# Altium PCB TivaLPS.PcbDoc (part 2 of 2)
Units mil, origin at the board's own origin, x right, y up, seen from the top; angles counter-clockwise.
Board outline 2370 x 2970 mil, 2 copper layers (TopLayer, BottomLayer), stack 30.45 mil thick; 141 components, 125 nets, 734 pads, 136 vias.
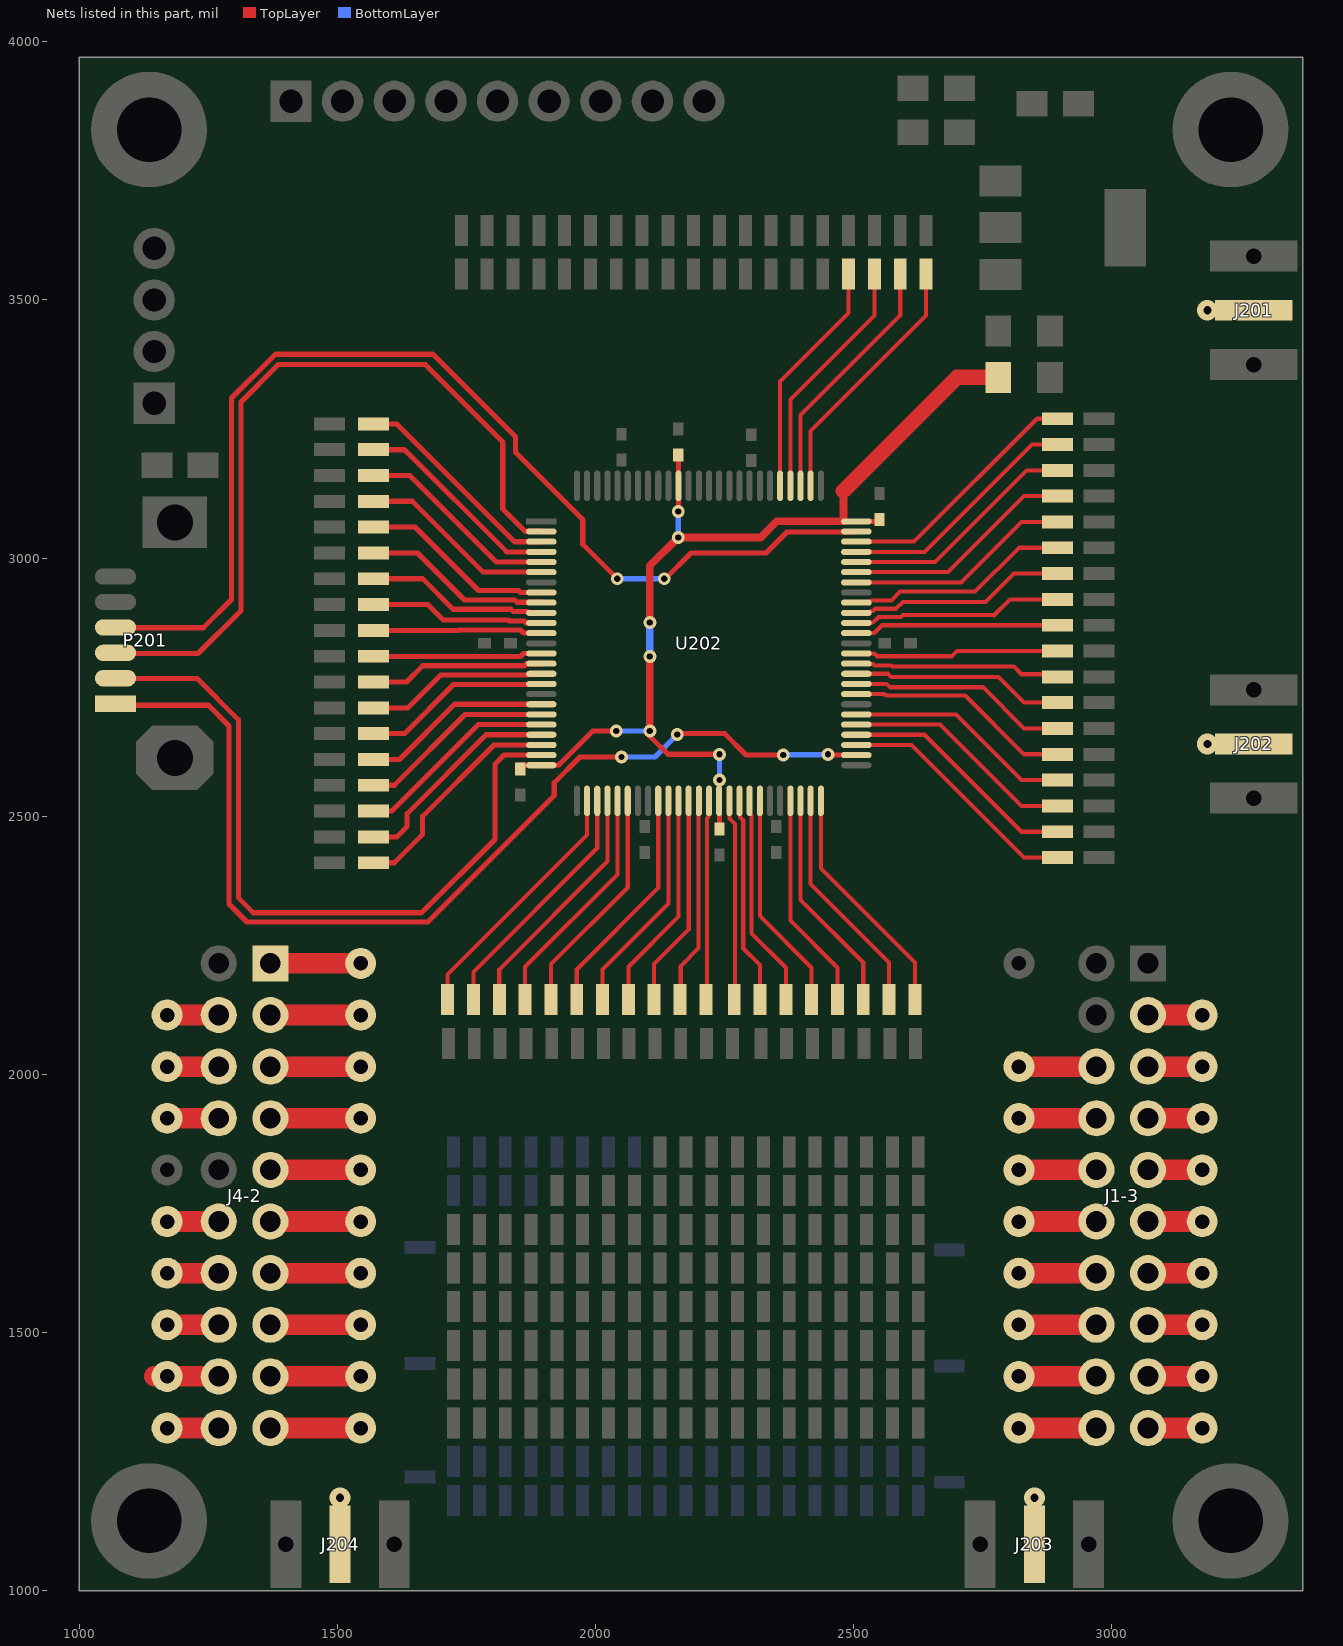
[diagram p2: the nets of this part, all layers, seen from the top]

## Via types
v1: diameter 25, hole 12, TopLayer to BottomLayer, 115 vias
v2: diameter 40, hole 16, TopLayer to BottomLayer, 19 vias
v3: diameter 40, hole 16, TopLayer to BottomLayer, tented top, 2 vias

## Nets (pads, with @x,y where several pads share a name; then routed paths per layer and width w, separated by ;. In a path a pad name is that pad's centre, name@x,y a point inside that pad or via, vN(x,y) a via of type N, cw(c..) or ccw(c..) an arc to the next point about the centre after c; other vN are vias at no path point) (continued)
NetTP216_1: TP216.1 U202.80 | length 464.8
  TopLayer w8: U202.80@2357.48,3140.12 2357.48,3342.48 2490,3475 TP216.1@2490,3550
NetTP217_1: TP217.1 U202.79 | length 477.3
  TopLayer w8: U202.79@2377.17,3140.12 2377.17,3307.17 2540,3470 TP217.1@2540,3550
NetTP218_1: TP218.1 U202.78 | length 489.9
  TopLayer w8: U202.78@2396.85,3140.12 2396.85,3276.85 2590,3470 TP218.1@2590,3550
NetTP219_1: TP219.1 U202.77 | length 502.4
  TopLayer w8: U202.77@2416.54,3140.12 2416.54,3246.54 2640,3470 TP219.1@2640,3550
NetTP233_1: TP233.1 U202.3 | length 419.4
  TopLayer w10: TP233.1@1570,3260 1615,3260 1843.15,3031.85 U202.3@1894.88,3031.85
NetTP234_1: TP234.1 U202.73 | length 488.5
  TopLayer w8: U202.73@2505.12,3031.85 2616.85,3031.85 2855,3270 TP234.1@2895,3270
NetTP237_1: TP237.1 U202.4 | length 406.8
  TopLayer w10: TP237.1@1570,3210 1630.04,3210 1827.88,3012.17 U202.4@1894.88,3012.17
NetTP238_1: TP238.1 U202.72 | length 476
  TopLayer w8: U202.72@2505.12,3012.17 2637.17,3012.17 2845,3220 TP238.1@2895,3220
NetTP241_1: TP241.1 U202.5 | length 394.3
  TopLayer w10: TP241.1@1570,3160 1640,3160 1807.52,2992.48 U202.5@1894.88,2992.48
NetTP242_1: TP242.1 U202.71 | length 463.4
  TopLayer w8: U202.71@2505.12,2992.48 2657.48,2992.48 2835,3170 TP242.1@2895,3170
NetTP243_1: TP243.1 U202.6 | length 381.7
  TopLayer w10: TP243.1@1570,3110 1645,3110 1782.2,2972.8 U202.6@1894.88,2972.8
NetTP244_1: TP244.1 U202.70 | length 450.9
  TopLayer w8: U202.70@2505.12,2972.8 2682.8,2972.8 2830,3120 TP244.1@2895,3120
NetTP245_1: TP245.1 U202.69 | length 438.3
  TopLayer w8: U202.69@2505.12,2953.11 2708.11,2953.11 2825,3070 TP245.1@2895,3070
NetTP246_1: TP246.1 U202.8 | length 377.3
  TopLayer w10: TP246.1@1570,3060 1650,3060 1773,2937 1850.71,2937 1854.28,2933.43 U202.8@1894.88,2933.43
NetTP247_1: TP247.1 U202.9 | length 364.8
  TopLayer w10: TP247.1@1570,3010 1655,3010 1746,2919 1843.25,2919 1847.75,2914.5 1894.12,2914.5 U202.9@1894.88,2913.74
NetTP248_1: TP248.1 U202.67 | length 433.9
  TopLayer w8: U202.67@2505.12,2913.74 2529.77,2913.74 2534.03,2918 2573,2918 2590,2935 2735,2935 2820,3020 TP248.1@2895,3020
NetTP249_1: TP249.1 U202.10 | length 352.2
  TopLayer w10: TP249.1@1570,2960 1665,2960 1724,2901 1835.8,2901 1840.3,2896.5 1868.32,2896.5 1870.42,2894.4 1894.54,2894.4 U202.10@1894.88,2894.06
NetTP250_1: TP250.1 U202.66 | length 421.3
  TopLayer w8: U202.66@2505.12,2894.06 2529.77,2894.06 2533.46,2897.74 2537.49,2897.74 2541.75,2902 2582,2902 2595,2915 2755,2915 2810,2970 TP250.1@2895,2970
NetTP251_1: TP251.1 U202.11 | length 339.6
  TopLayer w10: TP251.1@1570,2910 1675,2910 1705,2880 1831.34,2880 1832.84,2878.5 1861.96,2878.5 1865.74,2874.72 1894.54,2874.72 U202.11@1894.88,2874.37
NetTP252_1: TP252.1 U202.65 | length 409.4
  TopLayer w8: U202.65@2505.12,2874.37 2505.85,2875.1 2537.47,2875.1 2548.37,2886 2591,2886 2595,2890 2771,2890 2771.69,2889.31 2802.37,2920 TP252.1@2895,2920
NetTP253_1: TP253.1 U202.12 | length 327.5
  TopLayer w10: TP253.1@1570,2860 1733.94,2860 1734.44,2860.5 1854.5,2860.5 1860.32,2854.69 U202.12@1894.88,2854.69
NetTP254_1: TP254.1 U202.64 | length 396.2
  TopLayer w8: U202.64@2505.12,2854.69 2539.68,2854.69 2555,2870 TP254.1@2895,2870
NetTP255_1: TP255.1 U202.14 | length 327.5
  TopLayer w10: TP255.1@1570,2810 1570.5,2809.5 1854.5,2809.5 1860.32,2815.32 U202.14@1894.88,2815.32
NetTP256_1: TP256.1 U202.62 | length 396.2
  TopLayer w8: U202.62@2505.12,2815.32 2539.68,2815.32 2545,2810 2690,2810 2700,2820 TP256.1@2895,2820
NetTP258_1: TP258.1 U202.15 | length 339.6
  TopLayer w10: TP258.1@1570,2760 1633.5,2760 1665,2791.5 1861.96,2791.5 1865.74,2795.28 1894.54,2795.28 U202.15@1894.88,2795.63
NetTP259_1: TP259.1 U202.61 | length 400.5
  TopLayer w8: U202.61@2505.12,2795.63 2505.85,2794.9 2537.47,2794.9 2540.43,2791.95 2573.06,2791.95 2575,2790 2810,2790 2825,2775 2890,2775 TP259.1@2895,2770
NetTP262_1: TP262.1 U202.16 | length 352.2
  TopLayer w10: TP262.1@1570,2710 1636.5,2710 1700,2773.5 1868.32,2773.5 1870.42,2775.6 1894.54,2775.6 U202.16@1894.88,2775.95
NetTP263_1: TP263.1 U202.60 | length 413.1
  TopLayer w8: U202.60@2505.12,2775.95 2566.68,2775.95 2572.63,2770 2780,2770 2830,2720 TP263.1@2895,2720
NetTP266_1: TP266.1 U202.17 | length 364.8
  TopLayer w10: TP266.1@1570,2660 1630,2660 1725,2755 1847.25,2755 1847.75,2755.5 1894.12,2755.5 U202.17@1894.88,2756.26
NetTP267_1: TP267.1 U202.59 | length 425.6
  TopLayer w8: U202.59@2505.12,2756.26 2563.74,2756.26 2570,2750 2750,2750 2830,2670 TP267.1@2895,2670
NetTP270_1: TP270.1 U202.58 | length 438.2
  TopLayer w8: U202.58@2505.12,2736.57 2558.43,2736.57 2560,2735 2562.37,2735 2563.37,2734 2716,2734 2830,2620 TP270.1@2895,2620
NetTP273_1: TP273.1 U202.19 | length 369.2
  TopLayer w10: TP273.1@1570,2610 1620,2610 1726.89,2716.89 U202.19@1894.88,2716.89
NetTP276_1: TP276.1 U202.20 | length 381.7
  TopLayer w10: TP276.1@1570,2560 1610,2560 1747.2,2697.2 U202.20@1894.88,2697.2
NetTP277_1: TP277.1 U202.56 | length 442.6
  TopLayer w8: U202.56@2505.12,2697.2 2697.8,2697.2 2825,2570 TP277.1@2895,2570
NetTP280_1: TP280.1 U202.21 | length 394.3
  TopLayer w10: TP280.1@1570,2510 1605,2510 1772.52,2677.52 U202.21@1894.88,2677.52
NetTP281_1: TP281.1 U202.55 | length 455.1
  TopLayer w8: U202.55@2505.12,2677.52 2667.48,2677.52 2825,2520 TP281.1@2895,2520
NetTP284_1: TP284.1 U202.22 | length 421.5
  TopLayer w10: TP284.1@1570,2460 1615,2460 1635,2480 1635,2505 1787.83,2657.83 U202.22@1894.88,2657.83
NetTP285_1: TP285.1 U202.54 | length 467.7
  TopLayer w8: U202.54@2505.12,2657.83 2637.17,2657.83 2825,2470 TP285.1@2895,2470
NetTP288_1: TP288.1 U202.23 | length 439.9
  TopLayer w10: TP288.1@1570,2410 1610,2410 1665,2465 1665,2500 1803.15,2638.15 U202.23@1894.88,2638.15
NetTP289_1: TP289.1 U202.53 | length 480.2
  TopLayer w8: U202.53@2505.12,2638.15 2611.85,2638.15 2830,2420 TP289.1@2895,2420
NetTP292_1: TP292.1 U202.27 | length 496.7
  TopLayer w8: TP292.1@1713.46,2145.06 1713.46,2193.46 1983.46,2463.46 U202.27@1983.46,2529.88
NetTP293_1: TP293.1 U202.28 | length 484.1
  TopLayer w8: TP293.1@1763.46,2145.06 1763.46,2198.46 2003.15,2438.15 U202.28@2003.15,2529.88
NetTP294_1: TP294.1 U202.29 | length 471.5
  TopLayer w8: TP294.1@1813.46,2145.06 1813.46,2203.46 2022.83,2412.83 U202.29@2022.83,2529.88
NetTP295_1: TP295.1 U202.30 | length 459
  TopLayer w8: TP295.1@1863.46,2145.06 1863.46,2208.46 2042.52,2387.52 U202.30@2042.52,2529.88
NetTP296_1: TP296.1 U202.31 | length 446.4
  TopLayer w8: TP296.1@1913.46,2145.06 1913.46,2213.46 2062.2,2362.2 U202.31@2062.2,2529.88
NetTP297_1: TP297.1 U202.34 | length 450.2
  TopLayer w8: TP297.1@1963.46,2145.06 1963.46,2203.46 2121.26,2361.26 U202.34@2121.26,2529.88
NetTP298_1: TP298.1 U202.35 | length 437.6
  TopLayer w8: TP298.1@2013.46,2145.06 2013.46,2203.46 2140.94,2330.95 U202.35@2140.94,2529.88
NetTP299_1: TP299.1 U202.36 | length 425.1
  TopLayer w8: TP299.1@2063.46,2145.06 2063.46,2208.46 2160.63,2305.63 U202.36@2160.63,2529.88
NetTP300_1: TP300.1 U202.37 | length 412.5
  TopLayer w8: TP300.1@2113.46,2145.06 2113.46,2213.46 2180.32,2280.32 U202.37@2180.32,2529.88
NetTP301_1: TP301.1 U202.38 | length 400
  TopLayer w8: TP301.1@2163.46,2145.06 2165,2146.61 2165,2210 2199.5,2244.5 2199.5,2529.38 U202.38@2200,2529.88
NetTP302_1: TP302.1 U202.39 | length 387.4
  TopLayer w8: TP302.1@2213.46,2145.06 2215.5,2147.11 2215.5,2495.5 2218.96,2498.96 2218.96,2529.15 U202.39@2219.68,2529.88
NetTP303_1: TP303.1 U202.41 | length 390
  TopLayer w8: U202.41@2259.06,2529.88 2259.06,2495.95 2270,2485 2270,2146.61 TP303.1@2268.46,2145.06
NetTP304_1: TP304.1 U202.42 | length 401.3
  TopLayer w8: U202.42@2278.74,2529.88 2279.47,2529.15 2279.47,2498.16 2286,2491.63 2286,2244 2318.46,2211.54 TP304.1@2318.46,2145.06
NetTP305_1: TP305.1 U202.43 | length 413.8
  TopLayer w8: U202.43@2298.43,2529.88 2298.43,2505.23 2302,2501.65 2302,2273 2368.46,2206.54 TP305.1@2368.46,2145.06
NetTP306_1: TP306.1 U202.44 | length 426.4
  TopLayer w8: U202.44@2318.11,2529.88 2318.11,2306.89 2418.46,2206.54 TP306.1@2418.46,2145.06
NetTP307_1: TP307.1 U202.47 | length 422.6
  TopLayer w8: U202.47@2377.17,2529.88 2377.17,2297.83 2468.46,2206.54 TP307.1@2468.46,2145.06
NetTP308_1: TP308.1 U202.48 | length 435.2
  TopLayer w8: U202.48@2396.85,2529.88 2396.85,2338.15 2518.46,2216.54 TP308.1@2518.46,2145.06
NetTP309_1: TP309.1 U202.49 | length 447.7
  TopLayer w8: U202.49@2416.54,2529.88 2416.54,2368.46 2568.46,2216.54 TP309.1@2568.46,2145.06
NetTP310_1: TP310.1 U202.50 | length 460.3
  TopLayer w8: U202.50@2436.22,2529.88 2436.22,2398.78 2618.46,2216.54 TP310.1@2618.46,2145.06
PA2: J4-2.20 TP291.1 | length 100
  TopLayer w40: TP291.1@1170,1315 J4-2.20@1270,1315
PA3: J4-2.18 TP287.1 | length 125
  TopLayer w40: TP287.1@1145,1415 J4-2.18@1270,1415
PA4: J4-2.16 TP283.1 | length 100
  TopLayer w40: TP283.1@1170,1515 J4-2.16@1270,1515
PA5: J1-3.15 TP231.1 | length 105
  TopLayer w40: J1-3.15@3070,1515 TP231.1@3175,1515
PA6: J1-3.17 TP235.1 | length 105
  TopLayer w40: J1-3.17@3070,1415 TP235.1@3175,1415
PA7: J1-3.19 TP239.1 | length 105
  TopLayer w40: J1-3.19@3070,1315 TP239.1@3175,1315
PB0: J1-3.5 TP221.1 | length 105
  TopLayer w40: J1-3.5@3070,2015 TP221.1@3175,2015
PB1: J1-3.7 TP223.1 | length 105
  TopLayer w40: J1-3.7@3070,1915 TP223.1@3175,1915
PB2: J4-2.4 TP261.1 | length 100
  TopLayer w40: TP261.1@1170,2115 J4-2.4@1270,2115
PB3: J4-2.5 TP264.1 | length 175
  TopLayer w40: J4-2.5@1370,2015 TP264.1@1545,2015
PB4: J1-3.13 TP229.1 | length 105
  TopLayer w40: J1-3.13@3070,1615 TP229.1@3175,1615
PB5: J1-3.3 TP220.1 | length 105
  TopLayer w40: J1-3.3@3070,2115 TP220.1@3175,2115
PB6: J4-2.14 TP279.1 | length 100
  TopLayer w40: TP279.1@1170,1615 J4-2.14@1270,1615
PB7: J4-2.12 TP275.1 | length 100
  TopLayer w40: TP275.1@1170,1715 J4-2.12@1270,1715
PC4: J4-2.7 TP268.1 | length 175
  TopLayer w40: J4-2.7@1370,1915 TP268.1@1545,1915
PC5: J4-2.9 TP271.1 | length 175
  TopLayer w40: J4-2.9@1370,1815 TP271.1@1545,1815
PC6: J4-2.11 TP274.1 | length 175
  TopLayer w40: J4-2.11@1370,1715 TP274.1@1545,1715
PC7: J4-2.13 TP278.1 | length 175
  TopLayer w40: J4-2.13@1370,1615 TP278.1@1545,1615
PD0: J1-3.6 TP222.1 | length 150
  TopLayer w40: TP222.1@2820,2015 J1-3.6@2970,2015
PD1: J1-3.8 TP224.1 | length 150
  TopLayer w40: TP224.1@2820,1915 J1-3.8@2970,1915
PD2: J1-3.10 TP226.1 | length 150
  TopLayer w40: TP226.1@2820,1815 J1-3.10@2970,1815
PD3: J1-3.12 TP228.1 | length 150
  TopLayer w40: TP228.1@2820,1715 J1-3.12@2970,1715
PD6: J4-2.15 TP282.1 | length 175
  TopLayer w40: J4-2.15@1370,1515 TP282.1@1545,1515
PD7: J4-2.17 TP286.1 | length 175
  TopLayer w40: J4-2.17@1370,1415 TP286.1@1545,1415
PE0: J4-2.6 TP265.1 | length 100
  TopLayer w40: TP265.1@1170,2015 J4-2.6@1270,2015
PE1: J1-3.14 TP230.1 | length 150
  TopLayer w40: TP230.1@2820,1615 J1-3.14@2970,1615
PE2: J1-3.16 TP232.1 | length 150
  TopLayer w40: TP232.1@2820,1515 J1-3.16@2970,1515
PE3: J1-3.18 TP236.1 | length 150
  TopLayer w40: TP236.1@2820,1415 J1-3.18@2970,1415
PE4: J1-3.9 TP225.1 | length 105
  TopLayer w40: J1-3.9@3070,1815 TP225.1@3175,1815
PE5: J1-3.11 TP227.1 | length 105
  TopLayer w40: J1-3.11@3070,1715 TP227.1@3175,1715
PF0: J4-2.8 TP269.1 | length 100
  TopLayer w40: TP269.1@1170,1915 J4-2.8@1270,1915
PF1: J1-3.20 TP240.1 | length 150
  TopLayer w40: TP240.1@2820,1315 J1-3.20@2970,1315
PF2: J4-2.1 TP257.1 | length 175
  TopLayer w40: J4-2.1@1370,2215 TP257.1@1545,2215
PF3: J4-2.3 TP260.1 | length 175
  TopLayer w40: J4-2.3@1370,2115 TP260.1@1545,2115
PF4: J4-2.19 TP290.1 | length 175
  TopLayer w40: J4-2.19@1370,1315 TP290.1@1545,1315
RF1c: J201.1
  other v2: 3185,3480
RF2c: J202.1
  other v2: 3185,2640
RF3c: J203.1
  other v2: 2850,1180
RF4c: J204.1
  other v2: 1505,1180
TCKm: P201.2 U202.24 | length 1416.8
  TopLayer w10: P201.2@1080,2766.58 1228.43,2766.58 1308,2687 1308,2342 1337,2313 1663,2313 1805,2455 1805,2600.88 1822.58,2618.46 U202.24@1894.88,2618.46
TDIm: P201.3 U202.2 | length 1485
  TopLayer w10: P201.3@1045,2814.21 P201.3@1045.79,2813.43 ; P201.3@1090,2815 1230,2815 1313,2898 1313,3302.54 1385.46,3375 1670,3375 1820,3225 1820,3095.11 1863.23,3051.88 1894.54,3051.88 U202.2@1894.88,3051.54
TDOm: P201.4 U202.74 | length 2116.9
  TopLayer w10: P201.4@1100,2865 1240,2865 1295,2920 1295,3310 1380,3395 1685,3395 1845,3235 1845,3205 1975,3075 1975,3027 v1(2042,2960) ; v1(2133,2960) 2135,2960 2185,3010 2330,3010 2370.72,3050.72 2504.3,3050.72 U202.74@2505.12,3051.54
  BottomLayer w10: v1(2042,2960) v1(2133,2960)
TMSm: P201.1 U202.52 | length 1988.9
  TopLayer w10: P201.1@1076.58,2716.58 P201.1@1090,2716.58 ; P201.1@1090,2715 1250,2715 1290,2675 1290,2330 1325,2295 1675,2295 1920,2540 1920,2565 1970,2615 v1(2050,2615) ; v1(2158.12,2658.13) 2160,2660 2250,2660 2291.54,2618.46 v1@2363.4,2618.46 ; v1(2450,2620) 2451.19,2618.81 2504.77,2618.81 U202.52@2505.12,2618.46
  BottomLayer w10: v1(2050,2615) 2115,2615 v1(2158.12,2658.13) ; v1(2363.43,2618.43) 2364.22,2619.22 2449.22,2619.22 v1(2450,2620)
VDD18: C203.1 C204.1 C205.1 C206.1 FB201.2 U202.25 U202.40 U202.75 U202.90 | length 1991.1
  TopLayer w10: C203.1@1850,2598.78 U202.25@1894.88,2598.78 1895.23,2599.13 1928.67,2599.13 1994.54,2665 v1(2040,2665) ; v1(2105,2665) 2105,2655 2140,2620 v1(2240,2620) ; v1(2160,3090) 2160.31,3090.32 2160.31,3139.8 U202.90@2160.63,3140.12 2160.31,3140.43 2160.31,3189.69 C205.1@2160,3190 ; C204.1@2240,2470 2239.68,2470.32 2239.68,2529.88 2239.68,2570.19 v1(2240,2570.5) ; U202.75@2480,3071.22 U202.75@2505.12,3071.22 2546.22,3071.22 C206.1@2550,3075
  TopLayer w15: v1(2105,2665) v1(2105,2809.5) ; v1(2105,2875) 2105,2985 v1(2160,3040) 2320,3040 2351.22,3071.22 U202.75@2480,3071.22 ; U202.75@2480,3075 2480,3130
  TopLayer w30: 2480,3130 2700,3350 FB201.2@2780,3350
  BottomLayer w10: v1(2040,2665) v1(2105,2665) ; v1(2160,3040) v1(2160,3090) ; v1(2240,2570.5) v1(2240,2620)
  BottomLayer w15: v1(2105,2809.5) v1(2105,2875)
pads on no net: P202.1 P202.2 P202.3 P202.4
copper on no net: | length 67
  TopLayer w7: 1360.9,3677.5 1399.1,3732.5
  other v2: 1875,1840 1975,1840 2075,1840 1755,2310 1815,2365 2755,2385 2695,2440 1700,3280 2570,3320 1785,3360 2625,3375

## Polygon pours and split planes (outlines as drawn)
GNDm on BottomLayer "GNDM_L02_P002" (solid, pour order 2): 2690,1950 1655,1950 1655,1015 1020,1015 1020,3950 3350,3950 3350,1015 2690,1015

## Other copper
TopLayer:
  rectangle net GNDm: 2840,3485 3070,3760
  text "revA" at 1313,3753 h50
  text "KE0FF" at 1263.31,3679.89 h50
BottomLayer:
  text "01/01/22" at 1033,2228 h40 r270

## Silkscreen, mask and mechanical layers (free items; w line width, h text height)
TopOverlay:
  lines w7: 2218.2,1044 2248.2,1084
  lines w10: 1025,1845 1130,1845 ; 1396.8,2349.53 ccw(c1420,2365) 1439.72,2345.28 ; 1400.28,3299.72 cw(c1420,3280) 1443.2,3295.47 ; 1581,1915 1625,1915 ; 1581,2015 1621,1975 1625,1971 1625,1915 ; 1655.28,1999.72 ccw(c1675,1980) 1659.53,1956.8 ; 1700.28,3690.28 cw(c1720,3710) 1704.53,3733.21 ; 1735,1770 1715,1790 1715,1870 ; 1735,1850 1715,1870 ; 2655.47,3686.8 ccw(c2640,3710) 2659.72,3729.72 ; 2670.47,1956.8 ccw(c2655,1980) 2674.72,1999.72 ; 3016.8,2379.53 ccw(c3040,2395) 3059.72,2375.28 ; 3020.28,3319.72 cw(c3040,3300) 3063.2,3315.47 ; 1625,1915 1655,1885 1700,1885 1715,1870
  lines w30: 2995,3865 3090,3770 3090,3675
  text "+3.3V" at 2382,3792 h40
  text "GND" at 1572,3692 h40
  text "D" at 2567,3362 h35
  text "B" at 1817,3342 h35
  text "GND" at 1441.44,3323 h40 r90
  text "C" at 2512,3307 h35
  text "A" at 1732,3262 h35
  text "+3.3V" at 3173,2937 h40 r90
  text "+3.3V" at 1333,2427 h40 r90
  text "E" at 2642,2397 h35
  text "G" at 1757,2352 h35
  text "GND" at 2897,2352 h40
  text "F" at 2697,2342 h35
  text "H" at 1697,2292 h35
  text "J2-4" at 1175,2280 h60
  text "J3-1" at 2895,2280 h60
  text "GND" at 1683,2007 h40 r90
  text "GND" at 2693,2007 h40 r90
  text "+3.3V" at 1862,1864 h30
  text "RST" at 1032,1797 h35
  text "LC4256ZE-7TN100C" at 1810,1195 h50
  text "TIVA Interface" at 1805,1110 h60
  text "de KE0FF" at 2047,1047 h35
BottomOverlay:
  text "D" at 2590.33,3362 h35
  text "B" at 1842.25,3342.34 h35
  text "C" at 2535.33,3307 h35
  text "A" at 1755.33,3262 h35
  text "E" at 2663,2397 h35
  text "G" at 1778,2352 h35
  text "F" at 2723,2342 h35
  text "H" at 1720.33,2292 h35
  text "PF2" at 1685.3,2197 h35
  text "+5V" at 2768,2197 h35
  text "PB2" at 1120.3,2097 h35
  text "PF3" at 1683,2097 h35
  text "PB5" at 3320.3,2097 h35
  text "PE0" at 1120.3,1997 h35
  text "PB3" at 1683,1997 h35
  text "PD0" at 2765.3,1997 h35
  text "PB0" at 3323,1997 h35
  text "+3.3V" at 2226.94,1962 h40
  text "PF0" at 1120.3,1902 h35
  text "PD1" at 2768,1897 h35
  text "PB1" at 3308,1897 h35
  text "PC4" at 1668,1857 h35
  text "RST" at 1120.3,1797 h35
  text "PD2" at 2765.3,1797 h35
  text "PE4" at 3323,1797 h35
  text "PC5" at 1683,1782 h35
  text "PB7" at 1120.3,1697 h35
  text "PC6" at 1688,1697 h35
  text "PD3" at 2765.3,1697 h35
  text "PE5" at 3320.3,1697 h35
  text "PB6" at 1120.3,1597 h35
  text "PC7" at 1688,1597 h35
  text "PE1" at 2765.3,1597 h35
  text "PB4" at 3323,1597 h35
  text "PA4" at 1120.3,1497 h35
  text "PD6" at 1688,1497 h35
  text "PE2" at 2765.3,1497 h35
  text "PA5" at 3323,1497 h35
  text "PA3" at 1120.3,1397 h35
  text "PA6" at 3320.3,1397 h35
  text "PD7" at 1683,1377 h35
  text "PE3" at 2773,1377 h35
  text "PA2" at 1120.3,1302 h35
  text "PA7" at 3320.3,1302 h35
  text "PF4" at 1685.3,1297 h35
  text "PF1" at 2768,1287 h35
  text "GND" at 2198,1017 h30
TopSolder:
  region: 3071.32,3555 3071.32,3730 2891.32,3730 2891.32,3555
  lines w44: 1360,2365 1360,3280 ; 1420,2365 1420,3280 ; 1675,1920 2655,1920 ; 1675,1980 1995,1980 2335,1980 2655,1980 ; 1720,3710 2640,3710 ; 1720,3765 2685,3765 ; 3040,2395 3040,3300 ; 3095,2395 3095,3300
BottomSolder:
  rectangle: 2940,3550 3060,3730
  lines w44: 1675,1920 2655,1920
  lines w58: 1655,1080 2685,1080
Misc:
  text "TivaLPS, RevA ASSY Notes:" at 1030,7580 h58.33
  text "SEE SEPARATE BOM FOR PARTS TO PLACE" at 1030,7480 h58.33
  text "PARTS NOT LISTED IN BOM ARE DO-NOT-PLACE" at 1030,7380 h58.33
  text "ASSEMBLY FILES:" at 1030,7180 h58.33
  text "PASTE MASK: . . . . . . . . . . . . . . . . . . . . . . ." at 1030,7080 h58.33
  text "TivaLPS.GTP" at 3130,7060.56 h58.33
  text "PICK AND PLACE (CSV): . . . . . . . . . . . . . . . ." at 1030,6980 h58.33
  text "Pick Place for TivaLPS.csv" at 3130,6960.56 h58.33
  text "PICK AND PLACE (txt): . . . . . . . . . . . . . . . . ." at 1030,6880 h58.33
  text "Pick Place for TivaLPS.txt" at 3130,6860.56 h58.33
  text "BOM: . . . . . . . . . . . . . . . . . . . . . . . . . . . ." at 1030,6780 h58.33
  text "TivaLPS_BOM.xls" at 3130,6780 h58.33
  text "USE LEADED SOLDER PASTE, NO-CLEAN FLUX (NO-LEAD" at 1030,6580 h58.33
  text "SOLDER MAY BE SUBSTITUTED)" at 1130,6480 h58.33
  text "ASSEMBLE TOP SIDE SMD PARTS ONLY" at 1030,6380 h58.33
  text "NO THRU-HOLE OR HAND SOLDERING" at 1030,6280 h58.33
  text "PICK-PLACE FILES INCLUDE ALL COMPONENTS IN DESIGN," at 1030,6180 h58.33
  text "PLACE ONLY PARTS INDICATED IN BOM FILE" at 1130,6080 h58.33
  text "FOLLOW SILKSCREEN LEGEND TO ORIENT PARTS FOR (+)" at 1030,5980 h58.33
  text "OR PIN 1.  PIN 1 ON IC DEVICES IS ALSO INDICATED" at 1130,5880 h58.33
  text "BY RECTANGULAR PAD." at 1130,5780 h58.33
  text "INSPECT PER IPC-610 (CLASS 1) FOR WORKMANSHIP" at 1025,5680 h58.33
  text "NO FUNCTIONAL TEST REQUIRED" at 1025,5580 h58.33
Outline:
  the board outline again, w1
DrillDrawing:
  drawing of 327 lines, arcs and shapes, not listed
  text "TivaLP Shield PROJECT (RevA) CONTACT INFO:" at 4755,7563.33 h100
  text "Joe Haas" at 4755,7330 h100
  text "joeh@rollanet.org" at 4755,7130 h100
  text "4301 Yellowstone Dr." at 4755,6930 h100
  text "Taylor, TX 76574" at 4755,6730 h100
  text "+1 512-577-5575" at 4755,6530 h100
  text "TivaLPS, RevA PCB FAB Notes:" at 4695,6180 h58.33
  text "ALL DIMENSIONS IN MILS." at 4695,6080 h58.33
  text "MTL: FR-4, 0.031 THK +/- 5% (0.062 THK is an acceptable alternate)" at 4695,5988.33 h58.33
  text "BOARD EDGE DIMENSION TOLERANCE: +/- 10%" at 4695,5885 h58.33
  text "NUMBER OF COPPER LAYERS: 2, WT: 1 OZ" at 4695,5785 h58.33
  text "FINISH: LEADED HASL (LEAD-FREE OR ENIG MAY BE SUBSTITUTED)" at 4695,5685 h58.33
  text "SOLDERMASK: SMOBC, TWO SIDES, GREEN" at 4695,5585 h58.33
  text "SILKSCREEN: TOP ONLY, WHITE" at 4695,5485 h58.33
  text "HOLE SIZES ARE FINISHED DIMENSION" at 4695,5385 h58.33
  text "GERBER LAYER MAP:" at 4695,5185 h58.33
  text "LAYER STACKUP (FOR REFERENCE ONLY):" at 8805,5114.44 h58.33
  text "TivaLPS.GTO" at 6395,5090 h58.33
  text "TOP SILK: . . . . . . . . . . . . . . . . . . ." at 4695,5085 h58.33
  text "TivaLPS.GTS" at 6395,4990 h58.33
  text "TOP SOLDERMASK: . . . . . . . . . . . . . ." at 4695,4985 h58.33
  text "Layer" at 8860.56,4960 h60
  text "Name" at 9270.47,4960 h60
  text "Material" at 10140.23,4960 h60
  text "Thickness" at 11000,4960 h60
  text "Constant" at 11649.84,4960 h60
  text "Board Layer Stack" at 12219.7,4960 h60
  text "TivaLPS.GTL" at 6395,4890 h58.33
  text "TOP COPPER: . . . . . . . . . . . . . . . . ." at 4695,4885 h58.33
  text "TopOverlay" at 9270.47,4840 h60
  text "TivaLPS.GBL" at 6395,4790 h58.33
  text "BOTTOM COPPER: . . . . . . . . . . . . . ." at 4695,4785 h58.33
  text "TopSolder" at 9270.47,4720 h60
  text "Solder Resist" at 10140.23,4720 h60
  text "0.40mil" at 11000,4720 h60
  text "3.5" at 11649.84,4720 h60
  text "TivaLPS.GBS" at 6395,4695 h58.33
  text "BOTTOM SOLDERMASK: . . . . . . . . . . ." at 4695,4685 h58.33
  text "1" at 8860.56,4600 h60
  text "TopLayer" at 9270.47,4600 h60
  text "1.40mil" at 11000,4600 h60
  text "TivaLPS.GBO" at 6395,4590 h58.33
  text "BOTTOM SILK: . . . . . . . . . . . . . . . . ." at 4695,4585 h58.33
  text "TivaLPS.TXT" at 6395,4490 h58.33
  text "DRILL FILE: . . . . . . . . . . . . . . . . . . ." at 4695,4485 h58.33
  text "Dielectric1" at 9270.47,4480 h60
  text "FR-4" at 10140.23,4480 h60
  text "27.65mil" at 11000,4480 h60
  text "4.8" at 11649.84,4480 h60
  text "TivaLPS.DRR  (HOLE TOLERANCE +0/-0.003)" at 6395,4389.44 h58.33
  text "DRILL TOOL FILE: . . . . . . . . . . . . . . ." at 4695,4385 h58.33
  text "2" at 8860.56,4360 h60
  text "BottomLayer" at 9270.47,4360 h60
  text "1.40mil" at 11000,4360 h60
  text "DRILL/FAB DRAWING: . . . . . . . . . . . . ." at 4695,4293.33 h58.33
  text "TivaLPS.GD1  (THIS DWG)" at 6395,4284.44 h58.33
  text "BottomSolder" at 9270.47,4240 h60
  text "Solder Resist" at 10140.23,4240 h60
  text "0.40mil" at 11000,4240 h60
  text "3.5" at 11649.84,4240 h60
  text "BottomOverlay" at 9270.47,4120 h60
  text "Total board thickness:" at 8860.56,4000 h60
  text "31.25mil" at 11000,4000 h60
  text "PLACE PCB FAB DATE/MFR CODE ON BACK-SIDE SILKSCREEN" at 4695,3985 h58.33
  text "NARROW TRACE FOR BOARD OUTLINE (0.001 IN) IS FOR REFERENCE" at 4695,3885 h58.33
  text "ONLY, THIS ARTIFACT SHOULD BE REMOVED FROM THE FAB LAYERS" at 4795,3785 h58.33
  text "BEFORE PROCESSING." at 4795,3685 h58.33
  text "Symbol" at 4784.12,2425 h72
  text "Count" at 5290,2425 h72
  text "Hole Size" at 5889.84,2425 h72
  text "Plated" at 7029.51,2425 h72
  text "Hole Type" at 7535.38,2425 h72
  text "Drill Layer Pair" at 8269.19,2425 h72
  text "Via/Pad" at 9648.78,2425 h72
  text "Pad Shape" at 10238.62,2425 h72
  text "Template" at 10984.42,2425 h72
  text "Description" at 11724.22,2425 h72
  text "Hole Tolerance (+)" at 12577.98,2425 h72
  text "Hole Tolerance (-)" at 13911.59,2425 h72
  text "2" at 5290,2275 h60
  text "1.778mm (70.00mil)" at 5889.84,2275 h60
  text "PTH" at 7029.51,2275 h60
  text "Round" at 7535.38,2275 h60
  text "TopLayer - BottomLayer" at 8269.19,2275 h60
  text "Pad" at 9648.78,2275 h60
  text "(Mixed)" at 10238.62,2275 h60
  text "(Mixed)" at 10984.42,2275 h60
  text "4" at 5290,2125 h60
  text "3.175mm (125.00mil)" at 5889.84,2125 h60
  text "PTH" at 7029.51,2125 h60
  text "Round" at 7535.38,2125 h60
  text "TopLayer - BottomLayer" at 8269.19,2125 h60
  text "Pad" at 9648.78,2125 h60
  text "Rounded" at 10238.62,2125 h60
  text "c572h318" at 10984.42,2125 h60
  text "8" at 5290,1975 h60
  text "0.762mm (30.00mil)" at 5889.84,1975 h60
  text "PTH" at 7029.51,1975 h60
  text "Round" at 7535.38,1975 h60
  text "TopLayer - BottomLayer" at 8269.19,1975 h60
  text "Pad" at 9648.78,1975 h60
  text "Rectangle" at 10238.62,1975 h60
  text "r432_152h76" at 10984.42,1975 h60
  text "13" at 5290,1825 h60
  text "1.143mm (45.00mil)" at 5889.84,1825 h60
  text "PTH" at 7029.51,1825 h60
  text "Round" at 7535.38,1825 h60
  text "TopLayer - BottomLayer" at 8269.19,1825 h60
  text "Pad" at 9648.78,1825 h60
  text "(Mixed)" at 10238.62,1825 h60
  text "(Mixed)" at 10984.42,1825 h60
  text "21" at 5290,1675 h60
  text "0.406mm (16.00mil)" at 5889.84,1675 h60
  text "PTH" at 7029.51,1675 h60
  text "Round" at 7535.38,1675 h60
  text "TopLayer - BottomLayer" at 8269.19,1675 h60
  text "Via" at 9648.78,1675 h60
  text "Rounded" at 10238.62,1675 h60
  text "(Mixed)" at 10984.42,1675 h60
  text "37" at 5290,1525 h60
  text "0.711mm (28.00mil)" at 5889.84,1525 h60
  text "PTH" at 7029.51,1525 h60
  text "Round" at 7535.38,1525 h60
  text "TopLayer - BottomLayer" at 8269.19,1525 h60
  text "Pad" at 9648.78,1525 h60
  text "Rounded" at 10238.62,1525 h60
  text "c152h71m157" at 10984.42,1525 h60
  text "40" at 5290,1375 h60
  text "1.016mm (40.00mil)" at 5889.84,1375 h60
  text "PTH" at 7029.51,1375 h60
  text "Round" at 7535.38,1375 h60
  text "TopLayer - BottomLayer" at 8269.19,1375 h60
  text "Pad" at 9648.78,1375 h60
  text "(Mixed)" at 10238.62,1375 h60
  text "(Mixed)" at 10984.42,1375 h60
  text "115" at 5290,1225 h60
  text "0.305mm (12.00mil)" at 5889.84,1225 h60
  text "PTH" at 7029.51,1225 h60
  text "Round" at 7535.38,1225 h60
  text "TopLayer - BottomLayer" at 8269.19,1225 h60
  text "Via" at 9648.78,1225 h60
  text "Rounded" at 10238.62,1225 h60
  text "v64h30" at 10984.42,1225 h60
  text "240 Total" at 5290,1075 h60

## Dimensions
1000,3970 to 3370,3970 on DrillDrawing
1000,3970 to 3230,3830 on DrillDrawing
1000,3970 to 1135,3830 on DrillDrawing
1000,1000 to 1000,3970 on DrillDrawing
1000,1000 to 1135,3830 on DrillDrawing
1000,1000 to 1135,1135 on DrillDrawing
